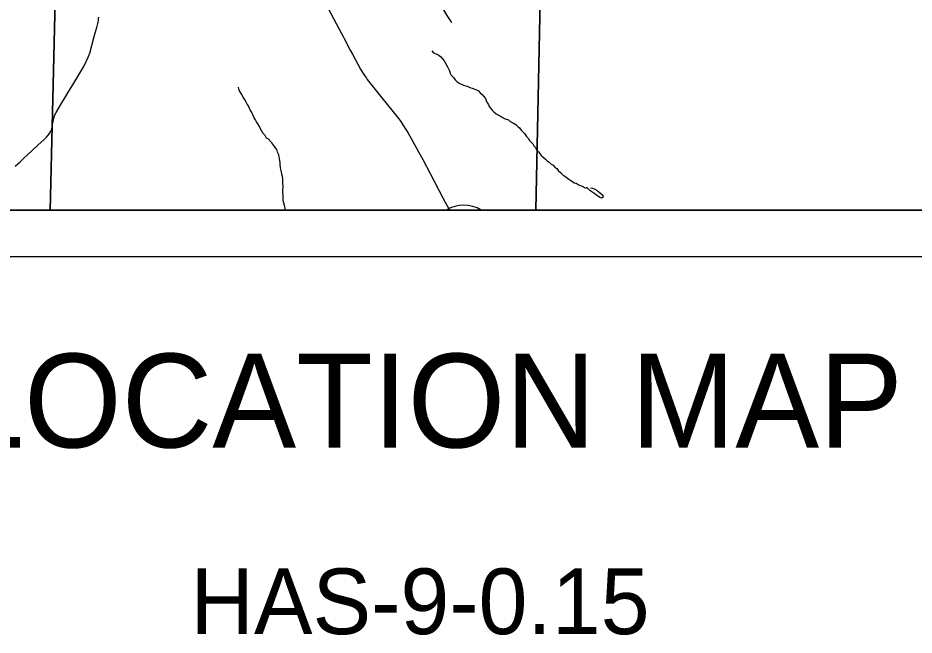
# Model space of a CAD drawing. Extents: x 0 to 34, y 0 to 22.
# Drawn here: x 5.063 to 6.972, y 12.694 to 14.01 of the extents above; entities that cross this region are included whole.
import ezdxf

# ---------------------------------------------------------------- set-up
doc = ezdxf.new("R2010")
doc.units = 0
for name, color, linetype in [('Default', 7, 'Continuous'), ('GM_X_Corporation', 7, 'Continuous'), ('GM_X_Minor_River', 7, 'Continuous'), ('GM_X_State_Route', 7, 'Continuous'), ('GM_X_Township_Road', 7, 'Continuous'), ('SH_Data', 7, 'Continuous'), ('SH_Text', 7, 'Continuous')]:
    doc.layers.add(name, color=color, linetype=linetype)

msp = doc.modelspace()

# ---------------------------------------------------------------- linework, layer by layer
at = {"layer": 'Default'}
msp.add_line((5.9751, 13.6), (6.0498, 13.6), dxfattribs=at)
msp.add_arc((6.0124, 13.5357), 0.0744, 59.8509, 120.1491, dxfattribs=at)
at = {"layer": 'GM_X_Corporation'}
for points in [[(2.6, 16.6918), (2.6, 13.6), (9.4, 13.6), (9.4, 16.4853), (9.09, 16.4927), (8.0963, 16.5226), (6.2194, 16.578), (6.0834, 16.5816), (5.4202, 16.5982), (4.6351, 16.6229), (4.5473, 16.6256), (4.1867, 16.6352), (4.1011, 16.6362), (4.0515, 16.6368), (3.1684, 16.6682), (3.1555, 16.6686)], [(4.5265, 13.6), (5.1312, 13.6), (5.155, 14.5827), (4.1372, 14.6117), (4.1159, 13.6143)], [(5.1312, 13.6), (6.1656, 13.6), (6.1855, 14.5629), (5.155, 14.5827)], [(6.1656, 13.6), (7.1626, 13.6), (7.1913, 14.5276), (6.1855, 14.5629)]]:
    msp.add_lwpolyline(points, close=True, dxfattribs=at)
msp.add_lwpolyline([(4.5781, 13.6), (9.4, 13.6), (9.4, 16.4853), (9.09, 16.4927), (8.0963, 16.5226), (6.2194, 16.578), (6.0834, 16.5816), (5.4202, 16.5982), (4.6351, 16.6229)], dxfattribs=at)
at = {"layer": 'GM_X_Minor_River'}
for points in [[(5.9443, 13.9397), (5.9474, 13.9356), (5.9512, 13.9337), (5.955, 13.9323), (5.9596, 13.9304), (5.9634, 13.9263), (5.9673, 13.9226), (5.9704, 13.9181), (5.9738, 13.9128), (5.9777, 13.9053), (5.9797, 13.9011), (5.982, 13.8966), (5.9832, 13.8917), (5.9859, 13.8876), (5.9902, 13.8827), (5.994, 13.8778), (5.9986, 13.8733), (6.0025, 13.8704), (6.0116, 13.8663), (6.0166, 13.8649), (6.0211, 13.8634), (6.0253, 13.8616), (6.0303, 13.8601), (6.0394, 13.8561), (6.0436, 13.8538), (6.0471, 13.8497), (6.0517, 13.846), (6.0551, 13.8422), (6.0586, 13.8377), (6.0602, 13.8336), (6.0625, 13.8287), (6.0649, 13.8249), (6.0668, 13.8208), (6.0691, 13.817), (6.0726, 13.8129), (6.0764, 13.8092), (6.0814, 13.805), (6.0875, 13.8013), (6.0921, 13.7995), (6.0963, 13.7969), (6.1009, 13.7947), (6.1074, 13.7921), (6.1112, 13.7891), (6.1158, 13.7869), (6.1196, 13.7847), (6.1234, 13.7821), (6.1273, 13.7784), (6.1311, 13.7754), (6.135, 13.7705), (6.1384, 13.7668), (6.1415, 13.763), (6.1458, 13.7566), (6.1496, 13.7529), (6.1527, 13.7484), (6.1558, 13.7446), (6.1592, 13.7409), (6.1619, 13.7367), (6.165, 13.733), (6.1677, 13.7285), (6.1716, 13.7244), (6.1743, 13.7206), (6.1774, 13.7165), (6.1812, 13.7131), (6.1866, 13.7086), (6.1904, 13.7049), (6.1946, 13.7019), (6.1989, 13.6978), (6.2027, 13.6959), (6.2065, 13.6911), (6.2104, 13.6885), (6.2138, 13.6843), (6.2192, 13.6795), (6.2234, 13.6754), (6.228, 13.672), (6.2364, 13.6661), (6.2403, 13.6631), (6.2441, 13.6609), (6.2479, 13.6583), (6.2517, 13.6572), (6.2563, 13.6542), (6.2605, 13.6524), (6.2651, 13.6509), (6.2693, 13.6483), (6.2735, 13.6468)], [(5.5658, 13.7967), (5.5627, 13.8032), (5.56, 13.8092), (5.5576, 13.8133), (5.5553, 13.8178), (5.5537, 13.822), (5.551, 13.8257), (5.5487, 13.8303), (5.5452, 13.8363), (5.5425, 13.8408), (5.5378, 13.8483), (5.5355, 13.8528), (5.5335, 13.8574), (5.5323, 13.8619)], [(5.6329, 13.6), (5.6318, 13.6043), (5.6306, 13.6096), (5.6297, 13.6134), (5.6286, 13.6171), (5.6277, 13.6217), (5.6273, 13.6255), (5.6271, 13.644), (5.6274, 13.649), (5.6272, 13.6596), (5.6267, 13.6675), (5.6263, 13.6717), (5.6251, 13.6766), (5.6239, 13.6811), (5.6227, 13.6868), (5.6222, 13.6906), (5.6214, 13.697), (5.621, 13.7008), (5.6205, 13.7057), (5.6201, 13.7095), (5.6189, 13.7137), (5.6185, 13.7175), (5.6157, 13.7231), (5.6138, 13.7288), (5.6114, 13.7325), (5.608, 13.7374), (5.6033, 13.743), (5.596, 13.7517), (5.5922, 13.7535), (5.5895, 13.7588), (5.5852, 13.7633), (5.5825, 13.7685), (5.5794, 13.7734), (5.5771, 13.7783), (5.574, 13.784), (5.5709, 13.7881), (5.5685, 13.7926), (5.5658, 13.7967)], [(6.2822, 13.6473), (6.2867, 13.6466), (6.2913, 13.6444), (6.2963, 13.6415), (6.3005, 13.6389), (6.3085, 13.6318), (6.3097, 13.6272), (6.306, 13.6253), (6.3021, 13.6271), (6.2972, 13.6301), (6.2895, 13.6361), (6.2849, 13.639), (6.2811, 13.642), (6.2773, 13.6454), (6.2742, 13.6491)]]:
    msp.add_lwpolyline(points, dxfattribs=at)
at = {"layer": 'GM_X_State_Route'}
msp.add_lwpolyline([(5.7224, 14.0327), (5.7349, 14.0087), (5.7465, 13.987), (5.756, 13.9686), (5.7569, 13.967), (5.7707, 13.9407), (5.7752, 13.9322), (5.7921, 13.9006), (5.7964, 13.8934), (5.801, 13.8865), (5.8051, 13.8808), (5.8068, 13.8785), (5.8209, 13.8602), (5.8375, 13.8393), (5.8588, 13.8132), (5.8709, 13.7982), (5.878, 13.7886), (5.8829, 13.7815), (5.8892, 13.772), (5.8935, 13.765), (5.9111, 13.7332), (5.916, 13.7239), (5.925, 13.7076), (5.9417, 13.6765), (5.968, 13.626), (5.9817, 13.6)], dxfattribs=at)
at = {"layer": 'GM_X_Township_Road'}
for points in [[(5.9872, 13.9998), (5.9771, 14.0144), (5.9611, 14.0417), (5.9419, 14.0752), (5.9318, 14.0933), (5.9307, 14.0958), (5.9294, 14.0994), (5.9285, 14.1023)], [(5.0569, 13.6936), (5.067, 13.7031), (5.0756, 13.7111), (5.082, 13.7169), (5.105, 13.738), (5.1185, 13.7505), (5.1236, 13.7557), (5.1272, 13.7597), (5.13, 13.7634), (5.1322, 13.7669), (5.1335, 13.7694), (5.1342, 13.7712), (5.1354, 13.7758), (5.1363, 13.7809), (5.1379, 13.79), (5.1388, 13.7949), (5.1398, 13.7988), (5.1406, 13.8011), (5.1413, 13.803), (5.1438, 13.8081), (5.1537, 13.8248), (5.1639, 13.8417), (5.1709, 13.8531), (5.1796, 13.8669), (5.1905, 13.8848), (5.1969, 13.8956), (5.2036, 13.9078), (5.2081, 13.9169), (5.2123, 13.926), (5.2154, 13.9348), (5.2201, 13.9509), (5.2241, 13.967), (5.2269, 13.9777), (5.2303, 13.9893), (5.2328, 13.9978), (5.2336, 14.0012), (5.2341, 14.0041), (5.2345, 14.0073), (5.2349, 14.0109)]]:
    msp.add_lwpolyline(points, dxfattribs=at)
at = {"layer": 'SH_Data'}
for points in [[(2.5, 20.5), (9.5, 20.5), (9.5, 13.5), (2.5, 13.5)], [(2.6, 20.4), (9.4, 20.4), (9.4, 13.6), (2.6, 13.6)]]:
    msp.add_lwpolyline(points, close=True, dxfattribs=at)

# ---------------------------------------------------------------- texts
at = {"layer": 'SH_Text'}
for s, height, p in [('LOCATION MAP', 0.2, (4.9269, 13.0938)), ('HAS-9-0.15', 0.14, (5.4302, 12.6959))]:
    msp.add_text(s, height=height, dxfattribs=at).set_placement(p)

doc.saveas('drawing.dxf')
